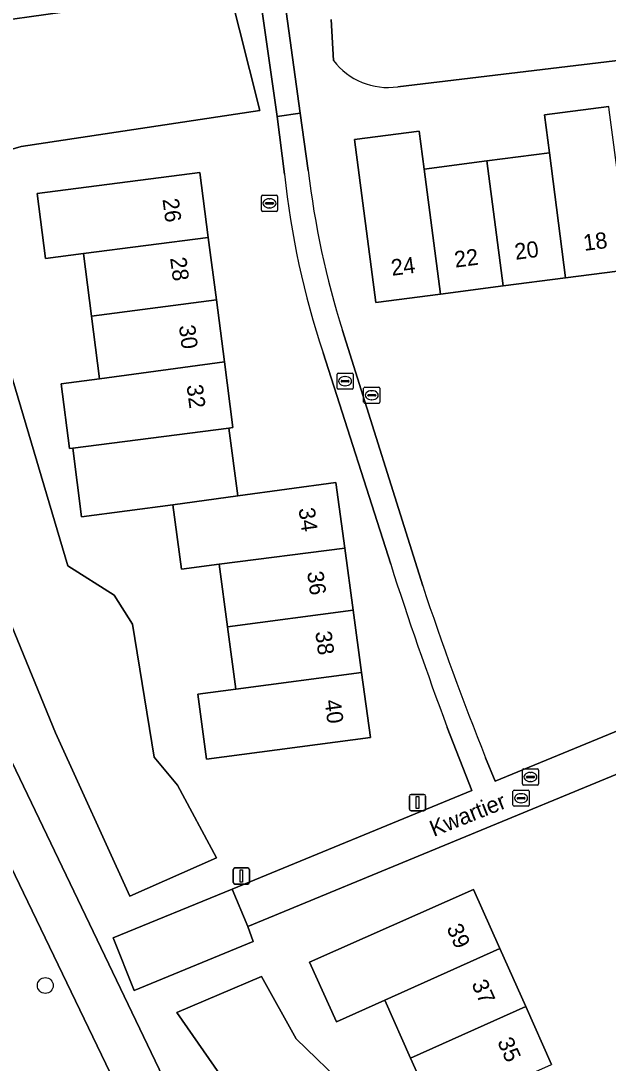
# Model space of a CAD drawing. Extents: x 159451 to 160664, y 388402 to 389723.
# Drawn here: x 159509 to 159545.2, y 389229 to 389293.3 of the extents above; entities that cross this region are included whole.
import ezdxf

# ---------------------------------------------------------------- set-up
doc = ezdxf.new("R2010")
doc.units = 0
for name, color, linetype in [('IMGEO_Boom', 7, 'Continuous'), ('IMGEO_Bouwland', 7, 'Continuous'), ('IMGEO_Grasland_overig', 7, 'Continuous'), ('IMGEO_Groenvoorziening', 7, 'Continuous'), ('IMGEO_Lichtmast', 7, 'Continuous'), ('IMGEO_Meer_plas_ven_vijver', 7, 'Continuous'), ('IMGEO_Openbare_ruimte_label', 7, 'Continuous'), ('IMGEO_Pand', 7, 'Continuous'), ('IMGEO_Pand_nummerreeks', 7, 'Continuous'), ('IMGEO_Rijbaan_lokaal_gesloten', 7, 'Continuous'), ('IMGEO_Rioolput', 7, 'Continuous')]:
    doc.layers.add(name, color=color, linetype=linetype)

msp = doc.modelspace()

# ---------------------------------------------------------------- linework, layer by layer
at = {"layer": 'IMGEO_Boom'}
msp.add_circle((159510.507, 389233.782), 0.489, dxfattribs=at)
at = {"layer": 'IMGEO_Bouwland'}
for points in [[(159521.25, 389297.74), (159493.172, 389293.777), (159486.712, 389292.863), (159536.847, 389188.304)], [(159525.256, 389283.811), (159524.796, 389287.372), (159523.669, 389295.299), (159523.555, 389296.061)], [(159531.804, 389259.756), (159527.637, 389272.799)], [(159580.373, 389208.403), (159573.107, 389227.927), (159563.374, 389252.707), (159559.597, 389251.864), (159562.085, 389239.938), (159557.562, 389237.923), (159558.351, 389236.161), (159554.447, 389234.413), (159550.543, 389232.664), (159545.842, 389243.23), (159548.614, 389244.465), (159547.283, 389247.447), (159522.997, 389237.416), (159523.334, 389236.494), (159515.988, 389233.475), (159514.682, 389236.714), (159522.027, 389239.718), (159536.816, 389245.805), (159535.285, 389249.699)], [(159534.626, 389225.732), (159533.03, 389229.303), (159531.434, 389232.875), (159528.453, 389231.539), (159526.807, 389235.21), (159536.903, 389239.704), (159538.532, 389236.056), (159540.13, 389232.476), (159541.724, 389228.904)]]:
    msp.add_lwpolyline(points, dxfattribs=at)
for points in [[(159511.894, 389259.653), (159514.744, 389257.84), (159515.886, 389256.055), (159517.22, 389247.851), (159518.659, 389246.126), (159521.069, 389241.65), (159515.724, 389239.283), (159511.127, 389249.352), (159494.743, 389289.39), (159494.831, 389290.177), (159496.278, 389291.663), (159521.85, 389295.267), (159523.74, 389287.733), (159509.011, 389285.515), (159504.61, 389284.226)], [(159529.489, 389256.929), (159530.008, 389253.087), (159530.55, 389249.068), (159520.446, 389247.737), (159519.913, 389251.738), (159522.256, 389252.051), (159521.746, 389255.905), (159521.237, 389259.759), (159518.902, 389259.462), (159518.374, 389263.415), (159512.749, 389262.686), (159512.202, 389266.91), (159512.009, 389266.885), (159511.491, 389270.881), (159513.854, 389271.198), (159513.355, 389275.058), (159512.856, 389278.918), (159510.521, 389278.616), (159510.008, 389282.625), (159520.041, 389283.908), (159520.557, 389279.914), (159521.057, 389276.054), (159521.551, 389272.231), (159522.073, 389268.192), (159521.819, 389268.158), (159522.384, 389263.975), (159528.428, 389264.791), (159528.974, 389260.743)], [(159525.975, 389230.482), (159529.13, 389227.44), (159531.217, 389225.185), (159533.719, 389221.109), (159538.578, 389214.693), (159539.985, 389209.42), (159541.252, 389201.297), (159536.188, 389201.27), (159531.83, 389210.522), (159523.869, 389224.551), (159518.626, 389232.107), (159523.847, 389234.341)]]:
    msp.add_lwpolyline(points, close=True, dxfattribs=at)
for centre, radius, start, end in [((159576.84, 389289.201), 51.865, 185.96525, 198.43596), ((159748.156, 389329.01), 227.166, 197.74989, 200.43436)]:
    msp.add_arc(centre, radius, start, end, dxfattribs=at)
at = {"layer": 'IMGEO_Grasland_overig'}
for points in [[(159486.712, 389292.863), (159483.087, 389292.351), (159491.324, 389276.977), (159493.1, 389273.212), (159500, 389258.58), (159504.093, 389250), (159534.245, 389187.399), (159541.062, 389164.374)], [(159543.868, 389152.492), (159543.663, 389144.191), (159543.127, 389122.477), (159551.705, 389123.07), (159550.85, 389135.446), (159552.375, 389144.269), (159550.196, 389160.656), (159546.355, 389164.126), (159540.689, 389183.824), (159539.945, 389186.409), (159538.67, 389189.107), (159536.847, 389188.304), (159486.712, 389292.863)]]:
    msp.add_lwpolyline(points, dxfattribs=at)
at = {"layer": 'IMGEO_Groenvoorziening'}
for points in [[(159525.003, 389296.267), (159525.136, 389295.518), (159526.226, 389287.573), (159526.723, 389284.029)], [(159528.272, 389290.814), (159528.13, 389293.352)], [(159556.966, 389290.126), (159546.129, 389290.863), (159532.239, 389289.197)], [(159546.592, 389277.935), (159542.577, 389277.414), (159538.735, 389276.916), (159534.868, 389276.415), (159530.881, 389275.898), (159529.576, 389285.954), (159533.569, 389286.469), (159533.872, 389284.123), (159537.733, 389284.625), (159541.594, 389285.127), (159541.295, 389287.473), (159545.256, 389287.981)], [(159528.825, 389274.169), (159533.776, 389258.43)], [(159541.062, 389164.374), (159534.245, 389187.399), (159504.093, 389250), (159500, 389258.58), (159493.1, 389273.212), (159487.441, 389272.575), (159530.224, 389180.456), (159534.303, 389168.702), (159537.243, 389155.693), (159538.081, 389141.023), (159539.156, 389122.203), (159543.127, 389122.477), (159543.663, 389144.191)], [(159537.657, 389247.809), (159538.251, 389246.377), (159550.467, 389251.425), (159550.122, 389253.843), (159547.128, 389253.464), (159545.873, 389263.038), (159550.103, 389263.588), (159549.974, 389264.586), (159554.246, 389265.142), (159555.492, 389255.556), (159558.754, 389255.947), (159559.116, 389254.331), (159562.054, 389254.997)]]:
    msp.add_lwpolyline(points, dxfattribs=at)
for centre, radius, start, end in [((159531.661, 389293.453), 4.295, 217.90944, 277.73769), ((159579.613, 389290.15), 53.243, 186.60177, 197.46708), ((159718.88, 389320.049), 195.091, 198.41199, 201.73344)]:
    msp.add_arc(centre, radius, start, end, dxfattribs=at)
at = {"layer": 'IMGEO_Lichtmast'}
for p, q in [((159533.063, 389245.559), (159533.853, 389245.559)), ((159533.853, 389245.559), (159533.063, 389245.559)), ((159532.963, 389244.659), (159532.963, 389245.459)), ((159532.963, 389245.459), (159532.963, 389244.659)), ((159533.953, 389245.459), (159533.953, 389244.659)), ((159533.953, 389244.659), (159533.953, 389245.459)), ((159533.853, 389244.559), (159533.063, 389244.559)), ((159533.063, 389244.559), (159533.853, 389244.559)), ((159522.2, 389241.032), (159522.99, 389241.032)), ((159522.99, 389241.032), (159522.2, 389241.032)), ((159522.1, 389240.132), (159522.1, 389240.932)), ((159522.1, 389240.932), (159522.1, 389240.132)), ((159523.09, 389240.932), (159523.09, 389240.132)), ((159523.09, 389240.132), (159523.09, 389240.932)), ((159522.99, 389240.032), (159522.2, 389240.032)), ((159522.2, 389240.032), (159522.99, 389240.032))]:
    msp.add_line(p, q, dxfattribs=at)
for points in [[(159533.383, 389245.434), (159533.533, 389245.434), (159533.533, 389244.684), (159533.383, 389244.684), (159533.383, 389245.434)], [(159522.52, 389240.907), (159522.67, 389240.907), (159522.67, 389240.157), (159522.52, 389240.157), (159522.52, 389240.907)]]:
    msp.add_lwpolyline(points, dxfattribs=at)
for centre, start, end in [((159533.063, 389245.459), 90, 180), ((159533.063, 389245.459), 90, 180), ((159533.853, 389245.459), 0, 90), ((159533.853, 389245.459), 360, 90), ((159533.063, 389244.659), 180, 270), ((159533.063, 389244.659), 180, 270), ((159533.853, 389244.659), 270, 0), ((159533.853, 389244.659), 270, 0), ((159522.2, 389240.932), 90, 180), ((159522.2, 389240.932), 90, 180), ((159522.99, 389240.932), 0, 90), ((159522.99, 389240.932), 360, 90), ((159522.2, 389240.132), 180, 270), ((159522.2, 389240.132), 180, 270), ((159522.99, 389240.132), 270, 0), ((159522.99, 389240.132), 270, 0)]:
    msp.add_arc(centre, 0.1, start, end, dxfattribs=at)
at = {"layer": 'IMGEO_Meer_plas_ven_vijver'}
for points in [[(159521.069, 389241.65), (159518.659, 389246.126), (159517.22, 389247.851), (159515.886, 389256.055), (159514.744, 389257.84), (159511.894, 389259.653), (159504.61, 389284.226), (159509.011, 389285.515), (159523.74, 389287.733), (159521.85, 389295.267), (159496.278, 389291.663), (159494.831, 389290.177), (159494.743, 389289.39), (159511.127, 389249.352), (159515.724, 389239.283)], [(159523.847, 389234.341), (159518.626, 389232.107), (159523.869, 389224.551), (159531.83, 389210.522), (159536.188, 389201.27), (159541.252, 389201.297), (159539.985, 389209.42), (159538.578, 389214.693), (159533.719, 389221.109), (159531.217, 389225.185), (159529.13, 389227.44), (159525.975, 389230.482)]]:
    msp.add_lwpolyline(points, close=True, dxfattribs=at)
for points in [[(159528.13, 389293.352), (159528.272, 389290.814)], [(159532.239, 389289.197), (159546.129, 389290.863), (159556.966, 389290.126)]]:
    msp.add_lwpolyline(points, dxfattribs=at)
msp.add_arc((159531.661, 389293.453), 4.295, 217.90944, 277.73769, dxfattribs=at)
at = {"layer": 'IMGEO_Pand'}
for points in [[(159545.281, 389287.787), (159545.256, 389287.981), (159541.295, 389287.473), (159541.594, 389285.127), (159542.577, 389277.414), (159546.592, 389277.935), (159546.558, 389278.199)], [(159533.872, 389284.123), (159533.569, 389286.469), (159529.576, 389285.954), (159530.881, 389275.898), (159534.868, 389276.415)], [(159541.594, 389285.127), (159537.733, 389284.625), (159538.735, 389276.916), (159542.577, 389277.414)], [(159537.733, 389284.625), (159533.872, 389284.123), (159534.868, 389276.415), (159538.735, 389276.916)], [(159520.041, 389283.908), (159510.008, 389282.625), (159510.521, 389278.616), (159512.856, 389278.918), (159520.557, 389279.914)], [(159520.557, 389279.914), (159512.856, 389278.918), (159513.355, 389275.058), (159521.057, 389276.054)], [(159521.057, 389276.054), (159513.355, 389275.058), (159513.854, 389271.198), (159521.551, 389272.231)], [(159521.551, 389272.231), (159513.854, 389271.198), (159511.491, 389270.881), (159512.009, 389266.885), (159512.202, 389266.91), (159521.819, 389268.158), (159522.073, 389268.192)], [(159521.819, 389268.158), (159512.202, 389266.91), (159512.749, 389262.686), (159518.374, 389263.415), (159522.384, 389263.975)], [(159528.428, 389264.791), (159522.384, 389263.975), (159518.374, 389263.415), (159518.902, 389259.462), (159521.237, 389259.759), (159528.974, 389260.743)], [(159528.974, 389260.743), (159521.237, 389259.759), (159521.746, 389255.905), (159529.489, 389256.929)], [(159529.489, 389256.929), (159521.746, 389255.905), (159522.256, 389252.051), (159530.008, 389253.087)], [(159530.008, 389253.087), (159522.256, 389252.051), (159519.913, 389251.738), (159520.446, 389247.737), (159530.55, 389249.068)], [(159538.532, 389236.056), (159536.903, 389239.704), (159526.807, 389235.21), (159528.453, 389231.539), (159531.434, 389232.875)], [(159538.532, 389236.056), (159531.434, 389232.875), (159533.03, 389229.303), (159540.13, 389232.476)], [(159540.13, 389232.476), (159533.03, 389229.303), (159534.626, 389225.732), (159541.724, 389228.904)]]:
    msp.add_lwpolyline(points, close=True, dxfattribs=at)
at = {"layer": 'IMGEO_Rijbaan_lokaal_gesloten'}
for points in [[(159525.136, 389295.518), (159523.669, 389295.299), (159524.796, 389287.372), (159526.226, 389287.573)], [(159522.997, 389237.416), (159522.027, 389239.718), (159514.682, 389236.714), (159515.988, 389233.475), (159523.334, 389236.494)]]:
    msp.add_lwpolyline(points, close=True, dxfattribs=at)
for points in [[(159526.723, 389284.029), (159526.226, 389287.573), (159524.796, 389287.372), (159525.256, 389283.811)], [(159533.776, 389258.43), (159528.825, 389274.169)], [(159527.637, 389272.799), (159531.804, 389259.756)], [(159550.467, 389251.425), (159538.251, 389246.377), (159537.657, 389247.809)], [(159535.285, 389249.699), (159536.816, 389245.805), (159522.027, 389239.718), (159522.997, 389237.416), (159547.283, 389247.447)]]:
    msp.add_lwpolyline(points, dxfattribs=at)
for centre, radius, start, end in [((159576.84, 389289.201), 51.865, 185.96525, 198.43596), ((159579.613, 389290.15), 53.243, 186.60177, 197.46708), ((159748.156, 389329.01), 227.166, 197.74989, 200.43436), ((159718.88, 389320.049), 195.091, 198.41199, 201.73344)]:
    msp.add_arc(centre, radius, start, end, dxfattribs=at)
at = {"layer": 'IMGEO_Rioolput'}
for p, q in [((159523.83, 389281.589), (159523.83, 389282.441)), ((159523.905, 389282.515), (159524.757, 389282.515)), ((159524.318, 389282.295), (159524.343, 389282.295)), ((159524.831, 389282.441), (159524.831, 389281.589)), ((159524.757, 389281.515), (159523.905, 389281.515)), ((159524.089, 389282.009), (159524.089, 389282.021)), ((159524.527, 389281.972), (159524.129, 389281.972)), ((159524.132, 389282.058), (159524.53, 389282.058)), ((159524.341, 389281.735), (159524.316, 389281.735)), ((159524.573, 389282.021), (159524.573, 389282.009)), ((159528.494, 389270.621), (159528.494, 389271.473)), ((159528.569, 389271.547), (159529.421, 389271.547)), ((159528.982, 389271.327), (159529.007, 389271.327)), ((159529.495, 389271.473), (159529.495, 389270.621)), ((159529.421, 389270.547), (159528.569, 389270.547)), ((159528.753, 389271.041), (159528.753, 389271.053)), ((159529.191, 389271.004), (159528.793, 389271.004)), ((159528.796, 389271.09), (159529.194, 389271.09)), ((159529.005, 389270.767), (159528.98, 389270.767)), ((159529.237, 389271.053), (159529.237, 389271.041)), ((159530.137, 389269.753), (159530.137, 389270.605)), ((159530.212, 389270.679), (159531.064, 389270.679)), ((159531.138, 389270.605), (159531.138, 389269.753)), ((159530.396, 389270.173), (159530.396, 389270.185)), ((159530.834, 389270.136), (159530.436, 389270.136)), ((159530.439, 389270.222), (159530.837, 389270.222)), ((159530.625, 389270.459), (159530.65, 389270.459)), ((159530.88, 389270.185), (159530.88, 389270.173)), ((159531.064, 389269.679), (159530.212, 389269.679)), ((159530.648, 389269.899), (159530.623, 389269.899)), ((159539.923, 389246.21), (159539.923, 389247.062)), ((159539.998, 389247.136), (159540.85, 389247.136)), ((159540.411, 389246.916), (159540.436, 389246.916)), ((159540.924, 389247.062), (159540.924, 389246.21)), ((159540.85, 389246.136), (159539.998, 389246.136)), ((159540.182, 389246.63), (159540.182, 389246.642)), ((159540.62, 389246.593), (159540.222, 389246.593)), ((159540.225, 389246.679), (159540.623, 389246.679)), ((159540.434, 389246.356), (159540.409, 389246.356)), ((159540.666, 389246.642), (159540.666, 389246.63)), ((159539.345, 389244.902), (159539.345, 389245.754)), ((159539.42, 389245.828), (159540.272, 389245.828)), ((159539.833, 389245.608), (159539.858, 389245.608)), ((159540.346, 389245.754), (159540.346, 389244.902)), ((159539.604, 389245.322), (159539.604, 389245.334)), ((159540.042, 389245.285), (159539.644, 389245.285)), ((159539.647, 389245.371), (159540.045, 389245.371)), ((159539.856, 389245.048), (159539.831, 389245.048)), ((159540.088, 389245.334), (159540.088, 389245.322)), ((159540.272, 389244.828), (159539.42, 389244.828))]:
    msp.add_line(p, q, dxfattribs=at)
for points in [[(159523.83, 389281.589), (159523.83, 389282.441)], [(159523.905, 389282.515), (159524.757, 389282.515)], [(159524.831, 389282.441), (159524.831, 389281.589)], [(159524.757, 389281.515), (159523.905, 389281.515)], [(159528.494, 389270.621), (159528.494, 389271.473)], [(159528.569, 389271.547), (159529.421, 389271.547)], [(159529.495, 389271.473), (159529.495, 389270.621)], [(159529.421, 389270.547), (159528.569, 389270.547)], [(159530.137, 389269.753), (159530.137, 389270.605)], [(159530.212, 389270.679), (159531.064, 389270.679)], [(159531.138, 389270.605), (159531.138, 389269.753)], [(159531.064, 389269.679), (159530.212, 389269.679)], [(159539.923, 389246.21), (159539.923, 389247.062)], [(159539.998, 389247.136), (159540.85, 389247.136)], [(159540.924, 389247.062), (159540.924, 389246.21)], [(159540.85, 389246.136), (159539.998, 389246.136)], [(159539.345, 389244.902), (159539.345, 389245.754)], [(159539.42, 389245.828), (159540.272, 389245.828)], [(159540.346, 389245.754), (159540.346, 389244.902)], [(159540.272, 389244.828), (159539.42, 389244.828)]]:
    msp.add_lwpolyline(points, dxfattribs=at)
for centre, radius, start, end in [((159523.907, 389282.439), 0.0765, 91.55205, 178.44795), ((159523.907, 389282.439), 0.0765, 91.55205, 178.44795), ((159524.755, 389282.439), 0.0765, 1.55205, 88.44795), ((159524.755, 389282.439), 0.0765, 1.55205, 88.44795), ((159523.907, 389281.591), 0.0765, 181.55205, 268.44795), ((159523.907, 389281.591), 0.0765, 181.55205, 268.44795), ((159524.129, 389282.018), 0.0403, 85.87752, 175.75265), ((159524.126, 389282.008), 0.0366, 178.93798, 274.71019), ((159524.53, 389282.015), 0.043, 264.86636, 352.45326), ((159524.534, 389282.02), 0.0386, 1.73085, 96.63898), ((159524.755, 389281.591), 0.0765, 271.55205, 358.44795), ((159524.755, 389281.591), 0.0765, 271.55205, 358.44795), ((159528.571, 389271.471), 0.0765, 91.55205, 178.44795), ((159528.571, 389271.471), 0.0765, 91.55205, 178.44795), ((159529.419, 389271.471), 0.0765, 1.55205, 88.44795), ((159529.419, 389271.471), 0.0765, 1.55205, 88.44795), ((159528.571, 389270.623), 0.0765, 181.55205, 268.44795), ((159528.571, 389270.623), 0.0765, 181.55205, 268.44795), ((159528.793, 389271.05), 0.0403, 85.87752, 175.75265), ((159528.79, 389271.04), 0.0366, 178.93798, 274.71019), ((159529.194, 389271.047), 0.043, 264.86636, 352.45326), ((159529.198, 389271.052), 0.0386, 1.73085, 96.63898), ((159529.419, 389270.623), 0.0765, 271.55205, 358.44795), ((159529.419, 389270.623), 0.0765, 271.55205, 358.44795), ((159530.214, 389270.603), 0.0765, 91.55205, 178.44795), ((159530.214, 389270.603), 0.0765, 91.55205, 178.44795), ((159531.062, 389270.603), 0.0765, 1.55205, 88.44795), ((159531.062, 389270.603), 0.0765, 1.55205, 88.44795), ((159530.436, 389270.182), 0.0403, 85.87752, 175.75265), ((159530.433, 389270.172), 0.0366, 178.93798, 274.71019), ((159530.837, 389270.179), 0.043, 264.86636, 352.45326), ((159530.841, 389270.184), 0.0386, 1.73085, 96.63898), ((159530.214, 389269.755), 0.0765, 181.55205, 268.44795), ((159530.214, 389269.755), 0.0765, 181.55205, 268.44795), ((159531.062, 389269.755), 0.0765, 271.55205, 358.44795), ((159531.062, 389269.755), 0.0765, 271.55205, 358.44795), ((159540, 389247.06), 0.0765, 91.55205, 178.44795), ((159540, 389247.06), 0.0765, 91.55205, 178.44795), ((159540.848, 389247.06), 0.0765, 1.55205, 88.44795), ((159540.848, 389247.06), 0.0765, 1.55205, 88.44795), ((159540, 389246.212), 0.0765, 181.55205, 268.44795), ((159540, 389246.212), 0.0765, 181.55205, 268.44795), ((159540.222, 389246.639), 0.0403, 85.87752, 175.75265), ((159540.219, 389246.629), 0.0366, 178.93798, 274.71019), ((159540.623, 389246.636), 0.043, 264.86636, 352.45326), ((159540.627, 389246.641), 0.0386, 1.73085, 96.63898), ((159540.848, 389246.212), 0.0765, 271.55205, 358.44795), ((159540.848, 389246.212), 0.0765, 271.55205, 358.44795), ((159539.422, 389245.752), 0.0765, 91.55205, 178.44795), ((159539.422, 389245.752), 0.0765, 91.55205, 178.44795), ((159540.27, 389245.752), 0.0765, 1.55205, 88.44795), ((159540.27, 389245.752), 0.0765, 1.55205, 88.44795), ((159539.422, 389244.904), 0.0765, 181.55205, 268.44795), ((159539.422, 389244.904), 0.0765, 181.55205, 268.44795), ((159539.644, 389245.331), 0.0403, 85.87752, 175.75265), ((159539.641, 389245.321), 0.0366, 178.93798, 274.71019), ((159540.045, 389245.328), 0.043, 264.86636, 352.45326), ((159540.049, 389245.333), 0.0386, 1.73085, 96.63898), ((159540.27, 389244.904), 0.0765, 271.55205, 358.44795), ((159540.27, 389244.904), 0.0765, 271.55205, 358.44795)]:
    msp.add_arc(centre, radius, start, end, dxfattribs=at)
for centre, major_axis, ratio, start_param, end_param in [((159524.317, 389282.015), (-0.387, 0.002), 0.722429, 4.712389, 7.853982), ((159524.342, 389282.015), (-0.39, 0.002), 0.717154, 1.570796, 4.712389), ((159528.981, 389271.047), (-0.387, 0.002), 0.722429, 4.712389, 7.853982), ((159529.006, 389271.047), (-0.39, 0.002), 0.717154, 1.570796, 4.712389), ((159530.624, 389270.179), (-0.387, 0.002), 0.722429, 4.712389, 7.853982), ((159530.649, 389270.179), (-0.39, 0.002), 0.717154, 1.570796, 4.712389), ((159540.41, 389246.636), (-0.387, 0.002), 0.722429, 4.712389, 7.853982), ((159540.435, 389246.636), (-0.39, 0.002), 0.717154, 1.570796, 4.712389), ((159539.832, 389245.328), (-0.387, 0.002), 0.722429, 4.712389, 7.853982), ((159539.857, 389245.328), (-0.39, 0.002), 0.717154, 1.570796, 4.712389)]:
    msp.add_ellipse(centre, major_axis=major_axis, ratio=ratio, start_param=start_param, end_param=end_param, dxfattribs=at)

# ---------------------------------------------------------------- texts
at = {"layer": 'IMGEO_Openbare_ruimte_label'}
msp.add_text('Kwartier', height=1, rotation=21.71629, dxfattribs=at).set_placement((159534.454, 389242.938))
at = {"layer": 'IMGEO_Pand_nummerreeks'}
for s, rotation, p in [('26', 277.36803, (159517.732, 389282.268)), ('18', 7.38543, (159543.744, 389279.078)), ('20', 7.38543, (159539.508, 389278.529)), ('22', 7.38543, (159535.789, 389278.047)), ('28', 277.36803, (159518.201, 389278.644)), ('24', 7.38543, (159531.892, 389277.542)), ('30', 277.36803, (159518.742, 389274.455)), ('32', 277.36803, (159519.216, 389270.788)), ('34', 277.68888, (159526.122, 389263.187)), ('36', 277.68888, (159526.65, 389259.271)), ('38', 277.68888, (159527.149, 389255.576)), ('40', 277.68888, (159527.719, 389251.351)), ('39', 294.05829, (159535.229, 389237.321)), ('37', 294.05829, (159536.766, 389233.879)), ('35', 294.05829, (159538.358, 389230.313))]:
    msp.add_text(s, height=1, rotation=rotation, dxfattribs=at).set_placement(p)

doc.saveas('drawing.dxf')
